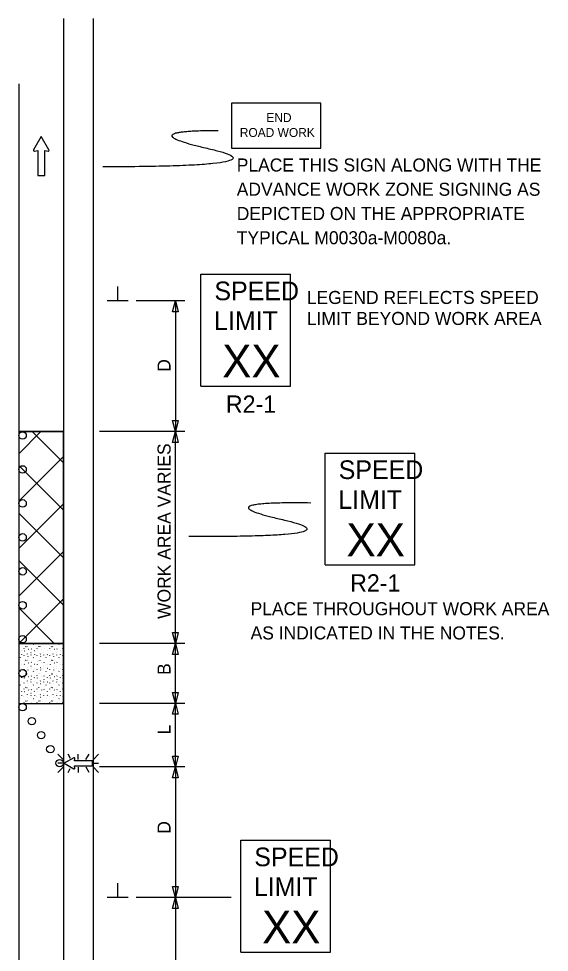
# Model space of a CAD drawing. Extents: x 16747 to 18480, y 5932 to 6927.
# Drawn here: x 17117 to 17402, y 6426 to 6927 of the extents above; entities that cross this region are included whole.
import ezdxf

# ---------------------------------------------------------------- set-up
doc = ezdxf.new("R2010")
doc.units = 0
for name, color, linetype in [('ALI_LEGAL_EX', 7, 'Continuous'), ('MT_SCRATCH_LEVEL_E', 7, 'Continuous'), ('PAVT_EDGE_EX', 7, 'Continuous'), ('TRAFFIC_SIGNS_PR', 7, 'Continuous'), ('TYPICAL_TEXT_DIMEN_PR', 7, 'Continuous')]:
    doc.layers.add(name, color=color, linetype=linetype)

msp = doc.modelspace()

# ---------------------------------------------------------------- linework, layer by layer
at = {"layer": 'ALI_LEGAL_EX'}
msp.add_line((17117.33, 6891.74), (17117.33, 6062.55), dxfattribs=at)
for points in [[(17117.33, 6891.74), (17117.33, 6866.74)], [(17117.33, 6791.74), (17117.33, 6766.74)], [(17117.33, 6691.74), (17117.33, 6666.74)], [(17117.33, 6591.74), (17117.33, 6566.74)], [(17117.33, 6491.74), (17117.33, 6466.74)]]:
    msp.add_lwpolyline(points, dxfattribs=at)
at = {"layer": 'MT_SCRATCH_LEVEL_E'}
for p, q in [((17129.43, 6863.57), (17125.32, 6856.33)), ((17129.43, 6863.57), (17125.32, 6856.33)), ((17133.58, 6856.33), (17129.43, 6863.57)), ((17133.58, 6856.33), (17129.43, 6863.57)), ((17125.8, 6855.64), (17127.58, 6855.96)), ((17125.8, 6855.64), (17127.58, 6855.96)), ((17127.58, 6855.96), (17127.58, 6842.7)), ((17127.58, 6855.96), (17127.58, 6842.7)), ((17131.32, 6842.7), (17131.32, 6855.96)), ((17131.32, 6855.96), (17133.1, 6855.64)), ((17131.32, 6842.7), (17131.32, 6855.96)), ((17131.32, 6855.96), (17133.1, 6855.64)), ((17127.58, 6842.7), (17131.32, 6842.7)), ((17127.58, 6842.7), (17131.32, 6842.7))]:
    msp.add_line(p, q, dxfattribs=at)
for centre, start, end in [((17125.73, 6856.1), 150.4248, 279.9638), ((17125.73, 6856.1), 150.4248, 279.9638), ((17133.17, 6856.1), 260.0362, 29.7731), ((17133.17, 6856.1), 260.0362, 29.7731)]:
    msp.add_arc(centre, 0.463, start, end, dxfattribs=at)
at = {"layer": 'PAVT_EDGE_EX'}
for p, q in [((17141.33, 6926.74), (17141.33, 6062.55)), ((17157.33, 6926.74), (17157.33, 6062.55)), ((17141.33, 6705.37), (17117.33, 6705.37)), ((17117.33, 6705.37), (17141.33, 6705.37)), ((17117.33, 6693.46), (17129.23, 6705.37)), ((17141.33, 6688.56), (17124.52, 6705.37)), ((17141.33, 6591.64), (17141.33, 6705.37)), ((17117.33, 6668.01), (17141.33, 6692.01)), ((17141.33, 6663.1), (17117.33, 6687.1)), ((17117.33, 6642.55), (17141.33, 6666.55)), ((17141.33, 6637.65), (17117.33, 6661.65)), ((17117.33, 6617.1), (17141.33, 6641.1)), ((17141.33, 6612.19), (17117.33, 6636.19)), ((17117.33, 6591.64), (17141.33, 6615.64)), ((17136.42, 6591.64), (17117.33, 6610.73)), ((17117.33, 6591.64), (17141.33, 6591.64)), ((17117.33, 6591.64), (17141.33, 6591.64)), ((17141.33, 6591.64), (17117.33, 6591.64)), ((17117.33, 6591.64), (17117.33, 6591.64)), ((17118.26, 6591.28), (17118.31, 6591.4)), ((17120.28, 6589.09), (17120.33, 6589.2)), ((17121.04, 6590.05), (17121.09, 6589.97)), ((17121.78, 6590.02), (17121.83, 6589.94)), ((17122.65, 6588.64), (17122.7, 6588.56)), ((17124.09, 6588.79), (17124.15, 6588.9)), ((17125.14, 6591.28), (17125.19, 6591.4)), ((17127.16, 6589.09), (17127.21, 6589.2)), ((17127.93, 6590.05), (17127.98, 6589.97)), ((17128.66, 6590.02), (17128.72, 6589.94)), ((17129.53, 6588.64), (17129.58, 6588.56)), ((17130.98, 6588.79), (17131.03, 6588.9)), ((17132.03, 6591.28), (17132.08, 6591.4)), ((17134.05, 6589.09), (17134.1, 6589.2)), ((17134.81, 6590.05), (17134.87, 6589.97)), ((17135.55, 6590.02), (17135.6, 6589.94)), ((17136.42, 6588.64), (17136.47, 6588.56)), ((17137.87, 6588.79), (17137.92, 6588.9)), ((17138.92, 6591.28), (17138.97, 6591.4)), ((17140.94, 6589.09), (17140.99, 6589.2)), ((17141.33, 6559.58), (17141.33, 6591.64)), ((17118.26, 6584), (17118.31, 6584.11)), ((17118.83, 6587.96), (17118.88, 6587.88)), ((17118.87, 6585.75), (17118.92, 6585.67)), ((17120.15, 6585.18), (17120.17, 6585.06)), ((17120.35, 6587.82), (17120.41, 6587.74)), ((17122, 6586.03), (17122.05, 6586.15)), ((17122.19, 6584.83), (17122.24, 6584.75)), ((17123.92, 6586.9), (17123.97, 6586.82)), ((17123.97, 6585.5), (17124.02, 6585.62)), ((17125.14, 6584), (17125.19, 6584.11)), ((17125.71, 6587.96), (17125.76, 6587.88)), ((17125.76, 6585.75), (17125.81, 6585.67)), ((17127.04, 6585.18), (17127.06, 6585.06)), ((17127.24, 6587.82), (17127.29, 6587.74)), ((17128.88, 6586.03), (17128.94, 6586.15)), ((17129.07, 6584.83), (17129.12, 6584.75)), ((17130.81, 6586.9), (17130.86, 6586.82)), ((17130.85, 6585.5), (17130.9, 6585.62)), ((17132.03, 6584), (17132.08, 6584.11)), ((17132.6, 6587.96), (17132.65, 6587.88)), ((17132.65, 6585.75), (17132.7, 6585.67)), ((17133.93, 6585.18), (17133.94, 6585.06)), ((17134.13, 6587.82), (17134.18, 6587.74)), ((17135.77, 6586.03), (17135.82, 6586.15)), ((17135.96, 6584.83), (17136.01, 6584.75)), ((17137.7, 6586.9), (17137.75, 6586.82)), ((17137.74, 6585.5), (17137.79, 6585.62)), ((17138.92, 6584), (17138.97, 6584.11)), ((17139.49, 6587.96), (17139.54, 6587.88)), ((17139.54, 6585.75), (17139.59, 6585.67)), ((17140.82, 6585.18), (17140.83, 6585.06)), ((17141.02, 6587.82), (17141.07, 6587.74)), ((17118.83, 6580.68), (17118.88, 6580.6)), ((17120.28, 6581.8), (17120.33, 6581.92)), ((17120.35, 6580.53), (17120.41, 6580.46)), ((17121.04, 6582.76), (17121.09, 6582.68)), ((17121.78, 6582.73), (17121.83, 6582.65)), ((17122, 6578.75), (17122.05, 6578.86)), ((17122.65, 6581.35), (17122.7, 6581.28)), ((17123.92, 6579.62), (17123.97, 6579.54)), ((17124.09, 6581.5), (17124.15, 6581.62)), ((17125.71, 6580.68), (17125.76, 6580.6)), ((17127.16, 6581.8), (17127.21, 6581.92)), ((17127.24, 6580.53), (17127.29, 6580.46)), ((17127.93, 6582.76), (17127.98, 6582.68)), ((17128.66, 6582.73), (17128.72, 6582.65)), ((17128.88, 6578.75), (17128.94, 6578.86)), ((17129.53, 6581.35), (17129.58, 6581.28)), ((17130.81, 6579.62), (17130.86, 6579.54)), ((17130.98, 6581.5), (17131.03, 6581.62)), ((17132.6, 6580.68), (17132.65, 6580.6)), ((17134.05, 6581.8), (17134.1, 6581.92)), ((17134.13, 6580.53), (17134.18, 6580.46)), ((17134.81, 6582.76), (17134.87, 6582.68)), ((17135.55, 6582.73), (17135.6, 6582.65)), ((17135.77, 6578.75), (17135.82, 6578.86)), ((17136.42, 6581.35), (17136.47, 6581.28)), ((17137.7, 6579.62), (17137.75, 6579.54)), ((17137.87, 6581.5), (17137.92, 6581.62)), ((17139.49, 6580.68), (17139.54, 6580.6)), ((17140.94, 6581.8), (17140.99, 6581.92)), ((17141.02, 6580.53), (17141.07, 6580.46)), ((17118.26, 6576.71), (17118.31, 6576.83)), ((17118.87, 6578.47), (17118.92, 6578.39)), ((17120.15, 6577.89), (17120.17, 6577.77)), ((17120.28, 6574.52), (17120.33, 6574.63)), ((17121.04, 6575.48), (17121.09, 6575.4)), ((17121.78, 6575.45), (17121.83, 6575.37)), ((17122.19, 6577.55), (17122.24, 6577.47)), ((17122.65, 6574.07), (17122.7, 6573.99)), ((17123.97, 6578.22), (17124.02, 6578.33)), ((17124.09, 6574.22), (17124.15, 6574.34)), ((17125.14, 6576.71), (17125.19, 6576.83)), ((17125.76, 6578.47), (17125.81, 6578.39)), ((17127.04, 6577.89), (17127.06, 6577.77)), ((17127.16, 6574.52), (17127.21, 6574.63)), ((17127.93, 6575.48), (17127.98, 6575.4)), ((17128.66, 6575.45), (17128.72, 6575.37)), ((17129.07, 6577.55), (17129.12, 6577.47)), ((17129.53, 6574.07), (17129.58, 6573.99)), ((17130.85, 6578.22), (17130.9, 6578.33)), ((17130.98, 6574.22), (17131.03, 6574.34)), ((17132.03, 6576.71), (17132.08, 6576.83)), ((17132.65, 6578.47), (17132.7, 6578.39)), ((17133.93, 6577.89), (17133.94, 6577.77)), ((17134.05, 6574.52), (17134.1, 6574.63)), ((17134.81, 6575.48), (17134.87, 6575.4)), ((17135.55, 6575.45), (17135.6, 6575.37)), ((17135.96, 6577.55), (17136.01, 6577.47)), ((17136.42, 6574.07), (17136.47, 6573.99)), ((17137.74, 6578.22), (17137.79, 6578.33)), ((17137.87, 6574.22), (17137.92, 6574.34)), ((17138.92, 6576.71), (17138.97, 6576.83)), ((17139.54, 6578.47), (17139.59, 6578.39)), ((17140.82, 6577.89), (17140.83, 6577.77)), ((17140.94, 6574.52), (17140.99, 6574.63)), ((17118.26, 6569.43), (17118.31, 6569.55)), ((17118.83, 6573.39), (17118.88, 6573.31)), ((17118.87, 6571.18), (17118.92, 6571.1)), ((17120.15, 6570.61), (17120.17, 6570.49)), ((17120.35, 6573.25), (17120.41, 6573.17)), ((17122, 6571.46), (17122.05, 6571.58)), ((17122.19, 6570.26), (17122.24, 6570.18)), ((17123.92, 6572.33), (17123.97, 6572.25)), ((17123.97, 6570.93), (17124.02, 6571.05)), ((17125.14, 6569.43), (17125.19, 6569.55)), ((17125.71, 6573.39), (17125.76, 6573.31)), ((17125.76, 6571.18), (17125.81, 6571.1)), ((17127.04, 6570.61), (17127.06, 6570.49)), ((17127.24, 6573.25), (17127.29, 6573.17)), ((17128.88, 6571.46), (17128.94, 6571.58)), ((17129.07, 6570.26), (17129.12, 6570.18)), ((17130.81, 6572.33), (17130.86, 6572.25)), ((17130.85, 6570.93), (17130.9, 6571.05)), ((17132.03, 6569.43), (17132.08, 6569.55)), ((17132.6, 6573.39), (17132.65, 6573.31)), ((17132.65, 6571.18), (17132.7, 6571.1)), ((17133.93, 6570.61), (17133.94, 6570.49)), ((17134.13, 6573.25), (17134.18, 6573.17)), ((17135.77, 6571.46), (17135.82, 6571.58)), ((17135.96, 6570.26), (17136.01, 6570.18)), ((17137.7, 6572.33), (17137.75, 6572.25)), ((17137.74, 6570.93), (17137.79, 6571.05)), ((17138.92, 6569.43), (17138.97, 6569.55)), ((17139.49, 6573.39), (17139.54, 6573.31)), ((17139.54, 6571.18), (17139.59, 6571.1)), ((17140.82, 6570.61), (17140.83, 6570.49)), ((17141.02, 6573.25), (17141.07, 6573.17)), ((17118.83, 6566.11), (17118.88, 6566.03)), ((17118.87, 6563.9), (17118.92, 6563.82)), ((17120.28, 6567.23), (17120.33, 6567.35)), ((17120.35, 6565.97), (17120.41, 6565.89)), ((17121.04, 6568.19), (17121.09, 6568.11)), ((17121.78, 6568.16), (17121.83, 6568.08)), ((17122, 6564.18), (17122.05, 6564.29)), ((17122.65, 6566.78), (17122.7, 6566.7)), ((17123.92, 6565.05), (17123.97, 6564.97)), ((17123.97, 6563.65), (17124.02, 6563.76)), ((17124.09, 6566.93), (17124.15, 6567.05)), ((17125.71, 6566.11), (17125.76, 6566.03)), ((17125.76, 6563.9), (17125.81, 6563.82)), ((17127.16, 6567.23), (17127.21, 6567.35)), ((17127.24, 6565.97), (17127.29, 6565.89)), ((17127.93, 6568.19), (17127.98, 6568.11)), ((17128.66, 6568.16), (17128.72, 6568.08)), ((17128.88, 6564.18), (17128.94, 6564.29)), ((17129.53, 6566.78), (17129.58, 6566.7)), ((17130.81, 6565.05), (17130.86, 6564.97)), ((17130.85, 6563.65), (17130.9, 6563.76)), ((17130.98, 6566.93), (17131.03, 6567.05)), ((17132.6, 6566.11), (17132.65, 6566.03)), ((17132.65, 6563.9), (17132.7, 6563.82)), ((17134.05, 6567.23), (17134.1, 6567.35)), ((17134.13, 6565.97), (17134.18, 6565.89)), ((17134.81, 6568.19), (17134.87, 6568.11)), ((17135.55, 6568.16), (17135.6, 6568.08)), ((17135.77, 6564.18), (17135.82, 6564.29)), ((17136.42, 6566.78), (17136.47, 6566.7)), ((17137.7, 6565.05), (17137.75, 6564.97)), ((17137.74, 6563.65), (17137.79, 6563.76)), ((17137.87, 6566.93), (17137.92, 6567.05)), ((17139.49, 6566.11), (17139.54, 6566.03)), ((17139.54, 6563.9), (17139.59, 6563.82)), ((17140.94, 6567.23), (17140.99, 6567.35)), ((17141.02, 6565.97), (17141.07, 6565.89)), ((17117.33, 6559.58), (17141.33, 6559.58)), ((17117.33, 6559.58), (17141.33, 6559.58)), ((17118.26, 6562.14), (17118.31, 6562.26)), ((17120.15, 6563.32), (17120.17, 6563.2)), ((17120.28, 6559.95), (17120.33, 6560.06)), ((17121.04, 6560.91), (17121.09, 6560.83)), ((17121.78, 6560.88), (17121.83, 6560.8)), ((17122.19, 6562.98), (17122.24, 6562.9)), ((17124.09, 6559.65), (17124.15, 6559.77)), ((17125.14, 6562.14), (17125.19, 6562.26)), ((17127.04, 6563.32), (17127.06, 6563.2)), ((17127.16, 6559.95), (17127.21, 6560.06)), ((17127.93, 6560.91), (17127.98, 6560.83)), ((17128.66, 6560.88), (17128.72, 6560.8)), ((17129.07, 6562.98), (17129.12, 6562.9)), ((17130.98, 6559.65), (17131.03, 6559.77)), ((17132.03, 6562.14), (17132.08, 6562.26)), ((17133.93, 6563.32), (17133.94, 6563.2)), ((17134.05, 6559.95), (17134.1, 6560.06)), ((17134.81, 6560.91), (17134.87, 6560.83)), ((17135.55, 6560.88), (17135.6, 6560.8)), ((17135.96, 6562.98), (17136.01, 6562.9)), ((17137.87, 6559.65), (17137.92, 6559.77)), ((17138.92, 6562.14), (17138.97, 6562.26)), ((17140.82, 6563.32), (17140.83, 6563.2)), ((17140.94, 6559.95), (17140.99, 6560.06))]:
    msp.add_line(p, q, dxfattribs=at)
at = {"layer": 'TRAFFIC_SIGNS_PR'}
for p, q in [((17215.06, 6789.69), (17263.06, 6789.69)), ((17215.06, 6729.69), (17215.06, 6789.69)), ((17263.06, 6729.69), (17263.06, 6789.69)), ((17215.06, 6729.69), (17263.06, 6729.69)), ((17281.7, 6693.81), (17329.7, 6693.81)), ((17281.7, 6633.81), (17281.7, 6693.81)), ((17329.7, 6633.81), (17329.7, 6693.81)), ((17281.7, 6633.81), (17329.7, 6633.81)), ((17138.37, 6532.3), (17141.19, 6529.48)), ((17145.09, 6530.11), (17143.83, 6532.3)), ((17149.28, 6529.48), (17149.28, 6532.3)), ((17153.41, 6529.48), (17155.04, 6532.3)), ((17157.36, 6529.48), (17160.18, 6532.3)), ((17141.19, 6527.45), (17138.37, 6527.45)), ((17138.37, 6522.6), (17141.19, 6525.41)), ((17143.81, 6522.6), (17145.01, 6524.69)), ((17149.28, 6525.41), (17149.28, 6522.6)), ((17155.06, 6522.6), (17153.44, 6525.41)), ((17157.36, 6527.45), (17160.18, 6527.45)), ((17157.36, 6525.41), (17160.18, 6522.59)), ((17236.44, 6486.17), (17284.44, 6486.17)), ((17236.44, 6426.17), (17236.44, 6486.17)), ((17284.44, 6426.17), (17284.44, 6486.17)), ((17236.44, 6426.17), (17284.44, 6426.17))]:
    msp.add_line(p, q, dxfattribs=at)
msp.add_lwpolyline([(17231.37, 6857.38), (17279.37, 6857.38), (17279.37, 6881.38), (17231.37, 6881.38)], close=True, dxfattribs=at)
for points in [[(17146.95, 6530.46), (17141.64, 6527.45), (17146.95, 6524.41)], [(17147.45, 6524.77), (17147.22, 6526.06), (17156.94, 6526.06), (17156.94, 6528.81), (17147.22, 6528.81), (17147.45, 6530.11)]]:
    msp.add_lwpolyline(points, dxfattribs=at)
for centre in [(17119.43, 6703.24), (17119.43, 6685.03), (17119.43, 6666.82), (17119.43, 6648.6), (17119.43, 6630.39), (17119.43, 6612.17), (17119.43, 6593.96), (17119.43, 6575.74), (17119.43, 6557.53), (17124.4, 6550.02), (17129.37, 6542.51), (17134.33, 6535.01), (17139.3, 6527.51)]:
    msp.add_circle(centre, 2, dxfattribs=at)
for centre, start, end in [((17147.11, 6530.16), 350.7308, 118.8916), ((17147.11, 6524.71), 241.4833, 9.9593)]:
    msp.add_arc(centre, 0.341, start, end, dxfattribs=at)
for points in [[(17224.3, 6866.63), (17177.06, 6866.63), (17262.08, 6847.28), (17162.37, 6847.28)], [(17273.94, 6667.02), (17216.02, 6667.85), (17301.04, 6648.5), (17208.57, 6649.05)]]:
    msp.add_open_spline(points, degree=2, dxfattribs=at)
at = {"layer": 'TYPICAL_TEXT_DIMEN_PR'}
for p, q in [((17170.45, 6775.37), (17170.45, 6783.15)), ((17176.08, 6775.37), (17164.83, 6775.37)), ((17206.33, 6775.37), (17180.33, 6775.37)), ((17199.76, 6769.5), (17201.33, 6775.37)), ((17201.33, 6775.37), (17201.33, 6705.37)), ((17201.33, 6775.37), (17202.9, 6769.5)), ((17201.33, 6769.5), (17199.76, 6769.5)), ((17202.9, 6769.5), (17201.33, 6769.5)), ((17201.33, 6705.37), (17199.76, 6711.23)), ((17199.76, 6711.23), (17201.33, 6711.23)), ((17201.33, 6711.23), (17202.9, 6711.23)), ((17202.9, 6711.23), (17201.33, 6705.37)), ((17206.33, 6705.37), (17160.63, 6705.37)), ((17199.76, 6699.5), (17201.33, 6705.37)), ((17201.33, 6591.64), (17201.33, 6705.37)), ((17201.33, 6705.37), (17202.9, 6699.5)), ((17201.33, 6699.5), (17199.76, 6699.5)), ((17202.9, 6699.5), (17201.33, 6699.5)), ((17201.33, 6591.64), (17199.76, 6597.5)), ((17199.76, 6597.5), (17201.33, 6597.5)), ((17201.33, 6597.5), (17202.9, 6597.5)), ((17202.9, 6597.5), (17201.33, 6591.64)), ((17206.33, 6591.64), (17160.63, 6591.64)), ((17199.76, 6585.78), (17201.33, 6591.64)), ((17201.33, 6559.58), (17201.33, 6591.64)), ((17201.33, 6591.64), (17202.9, 6585.78)), ((17201.33, 6585.78), (17199.76, 6585.78)), ((17202.9, 6585.78), (17201.33, 6585.78)), ((17201.33, 6559.58), (17199.76, 6565.44)), ((17199.76, 6565.44), (17201.33, 6565.44)), ((17201.33, 6565.44), (17202.9, 6565.44)), ((17202.9, 6565.44), (17201.33, 6559.58)), ((17206.33, 6559.58), (17160.63, 6559.58)), ((17199.76, 6553.72), (17201.33, 6559.58)), ((17201.33, 6525.47), (17201.33, 6559.58)), ((17201.33, 6559.58), (17202.9, 6553.72)), ((17201.33, 6553.72), (17199.76, 6553.72)), ((17202.9, 6553.72), (17201.33, 6553.72)), ((17201.33, 6525.47), (17199.76, 6531.33)), ((17199.76, 6531.33), (17201.33, 6531.33)), ((17201.33, 6531.33), (17202.9, 6531.33)), ((17202.9, 6531.33), (17201.33, 6525.47)), ((17206.33, 6525.47), (17160.63, 6525.47)), ((17199.76, 6519.61), (17201.33, 6525.47)), ((17201.33, 6525.47), (17201.33, 6455.47)), ((17201.33, 6525.47), (17202.9, 6519.61)), ((17201.33, 6519.61), (17199.76, 6519.61)), ((17202.9, 6519.61), (17201.33, 6519.61)), ((17201.33, 6480.34), (17201.33, 6476.57)), ((17170.45, 6455.47), (17170.45, 6463.26)), ((17201.33, 6455.47), (17199.76, 6461.33)), ((17199.76, 6461.33), (17201.33, 6461.33)), ((17201.33, 6461.33), (17202.9, 6461.33)), ((17202.9, 6461.33), (17201.33, 6455.47)), ((17176.08, 6455.47), (17164.83, 6455.47)), ((17231.25, 6455.47), (17180.33, 6455.47)), ((17199.76, 6449.61), (17201.33, 6455.47)), ((17201.33, 6455.47), (17201.33, 6385.47)), ((17201.33, 6455.47), (17202.9, 6449.61)), ((17201.33, 6449.61), (17199.76, 6449.61)), ((17202.9, 6449.61), (17201.33, 6449.61))]:
    msp.add_line(p, q, dxfattribs=at)

# ---------------------------------------------------------------- texts
at = {"layer": 'TRAFFIC_SIGNS_PR'}
for s, height, p in [('END', 4.789, (17250.12, 6871.29)), ('ROAD WORK', 4.789, (17235.88, 6863.31)), ('PLACE THIS SIGN ALONG WITH THE', 7, (17234.25, 6844.77)), ('ADVANCE WORK ZONE SIGNING AS', 7, (17234.25, 6831.77)), ('DEPICTED ON THE APPROPRIATE', 7, (17234.25, 6818.77)), ('TYPICAL M0030a-M0080a.', 7, (17234.25, 6805.77)), ('SPEED', 10, (17222.27, 6775.76)), ('LIMIT', 10, (17222.07, 6759.76)), ('XX', 17.538, (17226.45, 6734.38)), ('R2-1', 9.3, (17228.41, 6715.39)), ('SPEED', 10, (17288.91, 6679.88)), ('LIMIT', 10, (17288.7, 6663.88)), ('XX', 17.538, (17293.09, 6638.5)), ('R2-1', 9.3, (17295.04, 6619.51)), ('PLACE THROUGHOUT WORK AREA', 7, (17241.66, 6606.85)), ('AS INDICATED IN THE NOTES.', 7, (17241.66, 6593.85)), ('SPEED', 10, (17243.65, 6472.25)), ('LIMIT', 10, (17243.45, 6456.25)), ('XX', 17.538, (17247.83, 6430.87))]:
    msp.add_text(s, height=height, dxfattribs=at).set_placement(p)
at = {"layer": 'TYPICAL_TEXT_DIMEN_PR'}
for s, p in [('LEGEND REFLECTS SPEED', (17271.82, 6773.74)), ('LIMIT BEYOND WORK AREA', (17271.82, 6762.49))]:
    msp.add_text(s, height=7, dxfattribs=at).set_placement(p)
for s, p in [('D', (17198.77, 6737.39)), ('WORK AREA VARIES', (17198.77, 6604.86)), ('B', (17198.77, 6574.85)), ('L', (17198.77, 6542.87)), ('D', (17198.77, 6489.69))]:
    msp.add_text(s, height=7, rotation=90, dxfattribs=at).set_placement(p)

doc.saveas('drawing.dxf')
